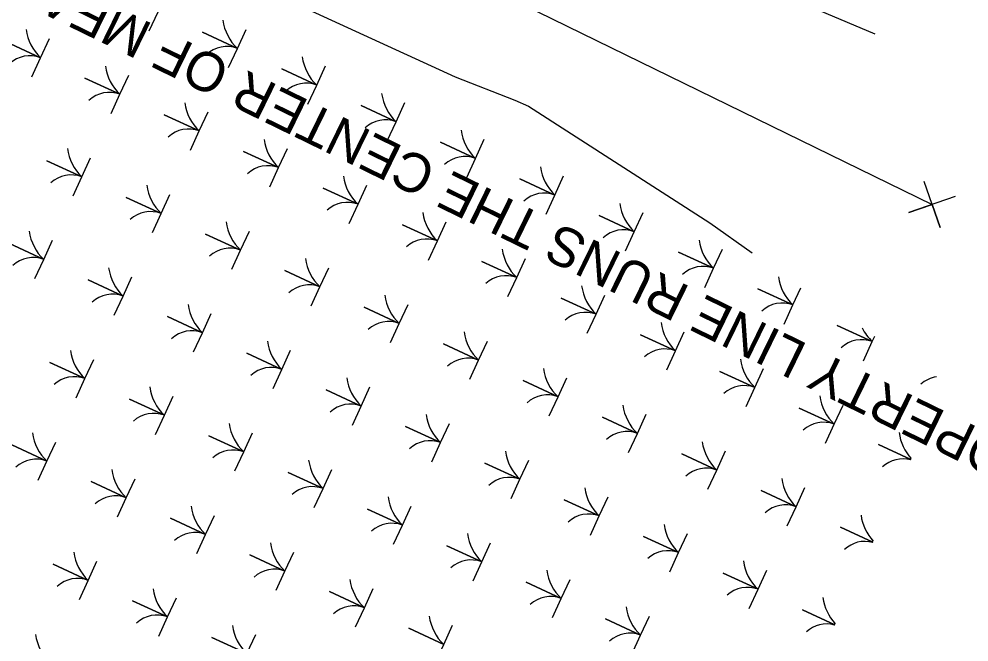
# Model space of a CAD drawing. Extents: x 2532037 to 2533565, y 713396 to 716867.
# Drawn here: x 2532941.6 to 2533038.9, y 715515.5 to 715579.2 of the extents above; entities that cross this region are included whole.
import ezdxf

# ---------------------------------------------------------------- set-up
doc = ezdxf.new("R2010")
doc.units = 0
for name, color, linetype in [('Exist Hydro Jurisdictional Stream or Body of Water', 7, 'Continuous'), ('Exist Property Corner CELL', 7, 'Continuous'), ('Exist Property Line', 7, 'Continuous'), ('Exist Property Line Text', 7, 'Continuous'), ('Scratch_Level_1', 7, 'Continuous')]:
    doc.layers.add(name, color=color, linetype=linetype)

msp = doc.modelspace()

# ---------------------------------------------------------------- linework, layer by layer
at = {"layer": 'Exist Hydro Jurisdictional Stream or Body of Water'}
for points in [[(2532929.47, 715622.835), (2532946.956, 715616.792), (2532952.272, 715615.056), (2532952.661, 715614.929), (2532976.224, 715605.737), (2532979.24, 715603.966), (2532987.717, 715600.698), (2532991.445, 715599.231), (2533013.51, 715585.624), (2533017.397, 715583.227), (2533021.385, 715580.964), (2533029.215, 715577.67)], [(2532927.478, 715598.382), (2532943.534, 715592.488), (2532944.699, 715591.96), (2532959.408, 715585.269), (2532965.064, 715583.035), (2532986.283, 715573.26), (2532992.386, 715570.894), (2532993.769, 715570.255), (2533012.334, 715558.335), (2533016.676, 715555.279)]]:
    msp.add_lwpolyline(points, dxfattribs=at)
at = {"layer": 'Exist Property Corner CELL'}
msp.add_line((2533035.08, 715560.215), (2533035.08, 715560.215), dxfattribs=at)
msp.add_lwpolyline([(2533037.444, 715561.027), (2533032.715, 715559.403), (2533035.08, 715560.215), (2533035.892, 715557.851), (2533034.268, 715562.579)], dxfattribs=at)
at = {"layer": 'Exist Property Line'}
msp.add_line((2532898.238, 715627.092), (2533035.08, 715560.215), dxfattribs=at)
at = {"layer": 'Scratch_Level_1'}
for points in [[(2532954.967, 715577.975), (2532955.868, 715579.927), (2532952.287, 715581.581), (2532955.868, 715579.927), (2532956.77, 715581.879)], [(2532963.089, 715574.225), (2532963.99, 715576.178), (2532960.408, 715577.831), (2532963.99, 715576.178), (2532964.891, 715578.13)], [(2532942.947, 715573.28), (2532943.849, 715575.232), (2532940.267, 715576.886), (2532943.849, 715575.232), (2532944.75, 715577.184)], [(2532971.21, 715570.476), (2532972.111, 715572.428), (2532968.529, 715574.082), (2532972.111, 715572.428), (2532973.013, 715574.381)], [(2532951.069, 715569.53), (2532951.97, 715571.483), (2532948.388, 715573.136), (2532951.97, 715571.483), (2532952.871, 715573.435)], [(2532979.331, 715566.726), (2532980.233, 715568.679), (2532976.651, 715570.332), (2532980.233, 715568.679), (2532981.134, 715570.631)], [(2532959.19, 715565.781), (2532960.091, 715567.733), (2532956.51, 715569.387), (2532960.091, 715567.733), (2532960.993, 715569.686)], [(2532987.453, 715562.977), (2532988.354, 715564.929), (2532984.772, 715566.583), (2532988.354, 715564.929), (2532989.256, 715566.882)], [(2532967.312, 715562.031), (2532968.213, 715563.984), (2532964.631, 715565.637), (2532968.213, 715563.984), (2532969.114, 715565.936)], [(2532947.17, 715561.086), (2532948.072, 715563.038), (2532944.49, 715564.692), (2532948.072, 715563.038), (2532948.973, 715564.991)], [(2532995.574, 715559.228), (2532996.476, 715561.18), (2532992.894, 715562.834), (2532996.476, 715561.18), (2532997.377, 715563.132)], [(2532975.433, 715558.282), (2532976.334, 715560.234), (2532972.752, 715561.888), (2532976.334, 715560.234), (2532977.236, 715562.187)], [(2532955.292, 715557.336), (2532956.193, 715559.289), (2532952.611, 715560.942), (2532956.193, 715559.289), (2532957.094, 715561.241)], [(2533003.696, 715555.478), (2533004.597, 715557.431), (2533001.015, 715559.084), (2533004.597, 715557.431), (2533005.498, 715559.383)], [(2532983.554, 715554.533), (2532984.456, 715556.485), (2532980.874, 715558.139), (2532984.456, 715556.485), (2532985.357, 715558.437)], [(2532963.413, 715553.587), (2532964.314, 715555.539), (2532960.733, 715557.193), (2532964.314, 715555.539), (2532965.216, 715557.492)], [(2532943.272, 715552.641), (2532944.173, 715554.594), (2532940.591, 715556.247), (2532944.173, 715554.594), (2532945.074, 715556.546)], [(2533011.817, 715551.729), (2533012.719, 715553.681), (2533009.137, 715555.335), (2533012.719, 715553.681), (2533013.62, 715555.634)], [(2532991.676, 715550.783), (2532992.577, 715552.736), (2532988.995, 715554.389), (2532992.577, 715552.736), (2532993.479, 715554.688)], [(2532971.535, 715549.838), (2532972.436, 715551.79), (2532968.854, 715553.444), (2532972.436, 715551.79), (2532973.337, 715553.743)], [(2532951.393, 715548.892), (2532952.295, 715550.844), (2532948.713, 715552.498), (2532952.295, 715550.844), (2532953.196, 715552.797)], [(2533019.939, 715547.98), (2533020.84, 715549.932), (2533017.258, 715551.586), (2533020.84, 715549.932), (2533021.656, 715551.699)], [(2532999.797, 715547.034), (2533000.699, 715548.986), (2532997.117, 715550.64), (2533000.699, 715548.986), (2533001.6, 715550.939)], [(2532979.656, 715546.088), (2532980.557, 715548.041), (2532976.975, 715549.694), (2532980.557, 715548.041), (2532981.459, 715549.993)], [(2532959.515, 715545.143), (2532960.416, 715547.095), (2532956.834, 715548.749), (2532960.416, 715547.095), (2532961.317, 715549.048)], [(2533028.06, 715544.23), (2533028.961, 715546.183), (2533025.38, 715547.836), (2533028.961, 715546.183), (2533029.217, 715546.735)], [(2533007.919, 715543.285), (2533008.82, 715545.237), (2533005.238, 715546.891), (2533008.82, 715545.237), (2533009.721, 715547.189)], [(2532987.777, 715542.339), (2532988.679, 715544.291), (2532985.097, 715545.945), (2532988.679, 715544.291), (2532989.58, 715546.244)], [(2532967.636, 715541.393), (2532968.537, 715543.346), (2532964.956, 715544.999), (2532968.537, 715543.346), (2532969.439, 715545.298)], [(2532947.495, 715540.448), (2532948.396, 715542.4), (2532944.814, 715544.054), (2532948.396, 715542.4), (2532949.297, 715544.353)], [(2533016.04, 715539.535), (2533016.942, 715541.488), (2533013.36, 715543.141), (2533016.942, 715541.488), (2533017.843, 715543.44)], [(2532995.899, 715538.59), (2532996.8, 715540.542), (2532993.218, 715542.196), (2532996.8, 715540.542), (2532997.702, 715542.494)], [(2532975.758, 715537.644), (2532976.659, 715539.596), (2532973.077, 715541.25), (2532976.659, 715539.596), (2532977.56, 715541.549)], [(2532955.616, 715536.698), (2532956.518, 715538.651), (2532952.936, 715540.304), (2532956.518, 715538.651), (2532957.419, 715540.603)], [(2533024.162, 715535.786), (2533025.063, 715537.738), (2533021.481, 715539.392), (2533025.063, 715537.738), (2533025.964, 715539.691)], [(2533004.02, 715534.84), (2533004.922, 715536.793), (2533001.34, 715538.446), (2533004.922, 715536.793), (2533005.823, 715538.745)], [(2532983.879, 715533.895), (2532984.78, 715535.847), (2532981.198, 715537.501), (2532984.78, 715535.847), (2532985.682, 715537.799)], [(2532963.738, 715532.949), (2532964.639, 715534.901), (2532961.057, 715536.555), (2532964.639, 715534.901), (2532965.54, 715536.854)], [(2532943.596, 715532.003), (2532944.498, 715533.956), (2532940.916, 715535.609), (2532944.498, 715533.956), (2532945.399, 715535.908)], [(2533032.895, 715534.123), (2533029.603, 715535.643), (2533032.895, 715534.123)], [(2533012.142, 715531.091), (2533013.043, 715533.043), (2533009.461, 715534.697), (2533013.043, 715533.043), (2533013.944, 715534.996)], [(2532971.859, 715529.2), (2532972.76, 715531.152), (2532969.179, 715532.806), (2532972.76, 715531.152), (2532973.662, 715533.104)], [(2532992, 715530.145), (2532992.902, 715532.098), (2532989.32, 715533.751), (2532992.902, 715532.098), (2532993.803, 715534.05)], [(2532951.718, 715528.254), (2532952.619, 715530.206), (2532949.037, 715531.86), (2532952.619, 715530.206), (2532953.52, 715532.159)], [(2533020.263, 715527.342), (2533021.164, 715529.294), (2533017.583, 715530.948), (2533021.164, 715529.294), (2533022.066, 715531.246)], [(2533000.122, 715526.396), (2533001.023, 715528.348), (2532997.441, 715530.002), (2533001.023, 715528.348), (2533001.925, 715530.301)], [(2532979.98, 715525.45), (2532980.882, 715527.403), (2532977.3, 715529.056), (2532980.882, 715527.403), (2532981.783, 715529.355)], [(2532959.839, 715524.505), (2532960.741, 715526.457), (2532957.159, 715528.111), (2532960.741, 715526.457), (2532961.642, 715528.409)], [(2533008.243, 715522.647), (2533009.145, 715524.599), (2533005.563, 715526.253), (2533009.145, 715524.599), (2533010.046, 715526.551)], [(2533029.006, 715525.674), (2533025.704, 715527.198), (2533029.006, 715525.674)], [(2532988.102, 715521.701), (2532989.003, 715523.653), (2532985.421, 715525.307), (2532989.003, 715523.653), (2532989.905, 715525.606)], [(2532967.961, 715520.755), (2532968.862, 715522.708), (2532965.28, 715524.361), (2532968.862, 715522.708), (2532969.763, 715524.66)], [(2532947.819, 715519.81), (2532948.721, 715521.762), (2532945.139, 715523.416), (2532948.721, 715521.762), (2532949.622, 715523.714)], [(2533016.365, 715518.897), (2533017.266, 715520.85), (2533013.684, 715522.503), (2533017.266, 715520.85), (2533018.167, 715522.802)], [(2532996.223, 715517.952), (2532997.125, 715519.904), (2532993.543, 715521.558), (2532997.125, 715519.904), (2532998.026, 715521.856)], [(2532976.082, 715517.006), (2532976.983, 715518.958), (2532973.402, 715520.612), (2532976.983, 715518.958), (2532977.885, 715520.911)], [(2532955.941, 715516.06), (2532956.842, 715518.013), (2532953.26, 715519.666), (2532956.842, 715518.013), (2532957.743, 715519.965)], [(2533025.118, 715517.225), (2533021.806, 715518.754), (2533025.118, 715517.225)], [(2533004.345, 715514.202), (2533005.246, 715516.155), (2533001.664, 715517.808), (2533005.246, 715516.155), (2533006.148, 715518.107)], [(2532984.203, 715513.257), (2532985.105, 715515.209), (2532981.523, 715516.863), (2532985.105, 715515.209), (2532986.006, 715517.161)], [(2532964.062, 715512.311), (2532964.963, 715514.263), (2532961.382, 715515.917), (2532964.963, 715514.263), (2532965.865, 715516.216)]]:
    msp.add_lwpolyline(points, dxfattribs=at)
for centre, radius, start, end in [((2532967.277, 715579.683), 4.806, 187.34643, 226.84116), ((2532947.136, 715578.737), 4.806, 187.34643, 226.84116), ((2532962.906, 715573.3), 3.075, 69.35932, 132.75394), ((2532942.765, 715572.355), 3.075, 69.35932, 132.75394), ((2532975.398, 715575.934), 4.806, 187.34643, 226.84116), ((2532955.257, 715574.988), 4.806, 187.34643, 226.84116), ((2532971.027, 715569.551), 3.075, 69.35932, 132.75394), ((2532950.886, 715568.605), 3.075, 69.35932, 132.75394), ((2532983.52, 715572.184), 4.806, 187.34643, 226.84116), ((2532963.379, 715571.239), 4.806, 187.34643, 226.84116), ((2532979.149, 715565.802), 3.075, 69.35932, 132.75394), ((2532959.008, 715564.856), 3.075, 69.35932, 132.75394), ((2532991.641, 715568.435), 4.806, 187.34643, 226.84116), ((2532971.5, 715567.489), 4.806, 187.34643, 226.84116), ((2532951.359, 715566.544), 4.806, 187.34643, 226.84116), ((2532987.27, 715562.052), 3.075, 69.35932, 132.75394), ((2532946.988, 715560.161), 3.075, 69.35932, 132.75394), ((2532967.129, 715561.107), 3.075, 69.35932, 132.75394), ((2532999.763, 715564.686), 4.806, 187.34643, 226.84116), ((2532979.621, 715563.74), 4.806, 187.34643, 226.84116), ((2532959.48, 715562.794), 4.806, 187.34643, 226.84116), ((2532995.392, 715558.303), 3.075, 69.35932, 132.75394), ((2532975.25, 715557.357), 3.075, 69.35932, 132.75394), ((2533007.884, 715560.936), 4.806, 187.34643, 226.84116), ((2532955.109, 715556.412), 3.075, 69.35932, 132.75394), ((2532987.743, 715559.991), 4.806, 187.34643, 226.84116), ((2532967.602, 715559.045), 4.806, 187.34643, 226.84116), ((2532947.46, 715558.099), 4.806, 187.34643, 226.84116), ((2533003.513, 715554.553), 3.075, 69.35932, 132.75394), ((2532983.372, 715553.608), 3.075, 69.35932, 132.75394), ((2533016.006, 715557.187), 4.806, 187.34643, 226.84116), ((2532963.231, 715552.662), 3.075, 69.35932, 132.75394), ((2532995.864, 715556.241), 4.806, 187.34643, 226.84116), ((2532943.089, 715551.717), 3.075, 69.35932, 132.75394), ((2532975.723, 715555.296), 4.806, 187.34643, 226.84116), ((2532955.582, 715554.35), 4.806, 187.34643, 226.84116), ((2533011.635, 715550.804), 3.075, 69.35932, 132.75394), ((2532991.493, 715549.858), 3.075, 69.35932, 132.75394), ((2533024.127, 715553.438), 4.806, 187.34643, 226.84116), ((2532971.352, 715548.913), 3.075, 69.35932, 132.75394), ((2533003.986, 715552.492), 4.806, 187.34643, 226.84116), ((2532951.211, 715547.967), 3.075, 69.35932, 132.75394), ((2532983.844, 715551.546), 4.806, 187.34643, 226.84116), ((2532963.703, 715550.601), 4.806, 187.34643, 226.84116), ((2533019.756, 715547.055), 3.075, 69.35932, 132.75394), ((2532999.615, 715546.109), 3.075, 69.35932, 132.75394), ((2532979.473, 715545.164), 3.075, 69.35932, 132.75394), ((2533012.107, 715548.743), 4.806, 187.34643, 226.84116), ((2532959.332, 715544.218), 3.075, 69.35932, 132.75394), ((2532991.966, 715547.797), 4.806, 187.34643, 226.84116), ((2533032.249, 715549.688), 4.806, 206.02085, 226.84116), ((2532971.825, 715546.851), 4.806, 187.34643, 226.84116), ((2533027.878, 715543.305), 3.075, 69.35932, 132.75394), ((2532951.683, 715545.906), 4.806, 187.34643, 226.84116), ((2533007.736, 715542.36), 3.075, 69.35932, 132.75394), ((2532987.595, 715541.414), 3.075, 69.35932, 132.75394), ((2533020.229, 715544.993), 4.806, 187.34643, 226.84116), ((2532967.454, 715540.469), 3.075, 69.35932, 132.75394), ((2533000.087, 715544.048), 4.806, 187.34643, 226.84116), ((2532947.312, 715539.523), 3.075, 69.35932, 132.75394), ((2532979.946, 715543.102), 4.806, 187.34643, 226.84116), ((2533035.999, 715539.556), 3.075, 98.8518, 132.75394), ((2532959.805, 715542.156), 4.806, 187.34643, 226.84116), ((2533015.858, 715538.61), 3.075, 69.35932, 132.75394), ((2532995.716, 715537.665), 3.075, 69.35932, 132.75394), ((2533028.35, 715541.244), 4.806, 187.34643, 226.84116), ((2532975.575, 715536.719), 3.075, 69.35932, 132.75394), ((2533008.209, 715540.298), 4.806, 187.34643, 226.84116), ((2532955.434, 715535.774), 3.075, 69.35932, 132.75394), ((2532988.067, 715539.353), 4.806, 187.34643, 226.84116), ((2532967.926, 715538.407), 4.806, 187.34643, 226.84116), ((2533003.838, 715533.915), 3.075, 69.35932, 132.75394), ((2533023.979, 715534.861), 3.075, 69.35932, 132.75394), ((2532947.785, 715537.461), 4.806, 187.34643, 226.84116), ((2532983.696, 715532.97), 3.075, 69.35932, 132.75394), ((2533036.472, 715537.494), 4.806, 187.34643, 222.77958), ((2532963.555, 715532.024), 3.075, 69.35932, 132.75394), ((2533016.33, 715536.549), 4.806, 187.34643, 226.84116), ((2532943.414, 715531.079), 3.075, 69.35932, 132.75394), ((2532996.189, 715535.603), 4.806, 187.34643, 226.84116), ((2533032.101, 715531.112), 3.075, 75.3536, 132.75394), ((2532955.906, 715533.712), 4.806, 187.34643, 226.84116), ((2532976.048, 715534.658), 4.806, 187.34643, 226.84116), ((2533011.959, 715530.166), 3.075, 69.35932, 132.75394), ((2532991.818, 715529.22), 3.075, 69.35932, 132.75394), ((2533024.452, 715532.799), 4.806, 187.34643, 226.84116), ((2532971.677, 715528.275), 3.075, 69.35932, 132.75394), ((2533004.31, 715531.854), 4.806, 187.34643, 226.84116), ((2532951.535, 715527.329), 3.075, 69.35932, 132.75394), ((2532984.169, 715530.908), 4.806, 187.34643, 226.84116), ((2532964.028, 715529.963), 4.806, 187.34643, 226.84116), ((2533020.081, 715526.417), 3.075, 69.35932, 132.75394), ((2532999.939, 715525.471), 3.075, 69.35932, 132.75394), ((2533032.573, 715529.05), 4.806, 187.34643, 222.92038), ((2532979.798, 715524.525), 3.075, 69.35932, 132.75394), ((2533012.432, 715528.104), 4.806, 187.34643, 226.84116), ((2532959.657, 715523.58), 3.075, 69.35932, 132.75394), ((2532992.29, 715527.159), 4.806, 187.34643, 226.84116), ((2532972.149, 715526.213), 4.806, 187.34643, 226.84116), ((2533028.202, 715522.667), 3.075, 75.14708, 132.75394), ((2532952.008, 715525.268), 4.806, 187.34643, 226.84116), ((2533008.061, 715521.722), 3.075, 69.35932, 132.75394), ((2532987.919, 715520.776), 3.075, 69.35932, 132.75394), ((2533020.553, 715524.355), 4.806, 187.34643, 226.84116), ((2532967.778, 715519.83), 3.075, 69.35932, 132.75394), ((2533000.412, 715523.409), 4.806, 187.34643, 226.84116), ((2532947.637, 715518.885), 3.075, 69.35932, 132.75394), ((2532980.271, 715522.464), 4.806, 187.34643, 226.84116), ((2532960.129, 715521.518), 4.806, 187.34643, 226.84116), ((2533016.182, 715517.972), 3.075, 69.35932, 132.75394), ((2532996.041, 715517.027), 3.075, 69.35932, 132.75394), ((2533028.675, 715520.606), 4.806, 187.34643, 223.06104), ((2532975.9, 715516.081), 3.075, 69.35932, 132.75394), ((2533008.533, 715519.66), 4.806, 187.34643, 226.84116), ((2532955.758, 715515.135), 3.075, 69.35932, 132.75394), ((2532988.392, 715518.714), 4.806, 187.34643, 226.84116), ((2532968.251, 715517.769), 4.806, 187.34643, 226.84116), ((2533024.304, 715514.223), 3.075, 74.94068, 132.75394), ((2532948.109, 715516.823), 4.806, 187.34643, 226.84116), ((2533004.162, 715513.277), 3.075, 69.35932, 132.75394)]:
    msp.add_arc(centre, radius, start, end, dxfattribs=at)

# ---------------------------------------------------------------- texts
at = {"layer": 'Exist Property Line Text'}
msp.add_text('PROPERTY LINE RUNS THE CENTER OF MEADOW BRANCH', height=4, rotation=153.95434, dxfattribs=at).set_placement((2533050.265, 715532.289))

doc.saveas('drawing.dxf')
